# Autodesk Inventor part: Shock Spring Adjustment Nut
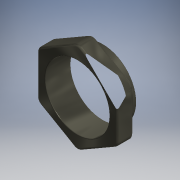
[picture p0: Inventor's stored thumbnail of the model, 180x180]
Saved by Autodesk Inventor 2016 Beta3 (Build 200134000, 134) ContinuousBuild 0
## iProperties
Shininess: 50.0
Compacted: True
Length Units: 11272
Angle Units: 11279
Time Units: 11290
Mass Units: 11286
Length Display Precision: 4
Angle Display Precision: 2
Company: Autodesk
Created: 2000-03
Part Number: Shock Spring Adjustment Nut
Project: Inventor Samples
User Status: IN PROGRESS
Document SubType Name: Modeling
Designer: Autodesk, Inc.
Density: 1.13 g/cm^3
Mass: 0.350545 g
Surface Area: 6.09851 cm^2
Volume: 0.310217 cm^3
Material: Nylon-6/6
Appearance: Gunmetal
Density: 0.0
Volumn: 0.0
Area: 0.0
PropertySet Name: Model Information
Control State: 0
Master: False
Checked Out: False
Author: Autodesk, Inc.
Revision Number: A
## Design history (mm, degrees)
node "Extrusion1" dims "d1" = 1.905, "d2" = 0
  sketch "Sketch2"
    geometry: C1 r 6.668 at (-5.692, -2.081)
    constraints: 1 centre point
    dimensions: "d0" = 13.335 diameter of C1
node "Extrusion2" dims "d4" = 3.175, "d5" = 0
  sketch "Sketch3"
    geometry: L1 (-7.938, -4.583)-(-7.938, 4.583); L2 (-7.938, 4.583)-(0, 9.165); L3 (0, 9.165)-(7.938, 4.583); L4 (7.938, 4.583)-(7.938, -4.583); L5 (7.938, -4.583)-(0, -9.165); L6 (0, -9.165)-(-7.938, -4.583); C1 r 7.938 at (0, 0); C2 r 6.668 at (0, 0) reference
    constraints: 12 end point, 6 tangent, 4 equal length, 1 centre point, 1 concentric, 1 parallel, 1 vertical
    dimensions: "d3" = 15.875 diameter of C1
node "Extrusion3" dims "d7" = 3.175, "d8" = 0
  sketch "Sketch4"
    geometry: C1 r 6.35 at (0, 0); C2 r 6.668 at (0, 0) reference
    constraints: 1 centre point, 1 coincident
    dimensions: "d6" = 12.7 diameter of C1
node "Fillet1" dims "d9" = 1.27
node "Fillet2" dims "d10" = 0.381, "d11" = 0.127
body "Solid1"
